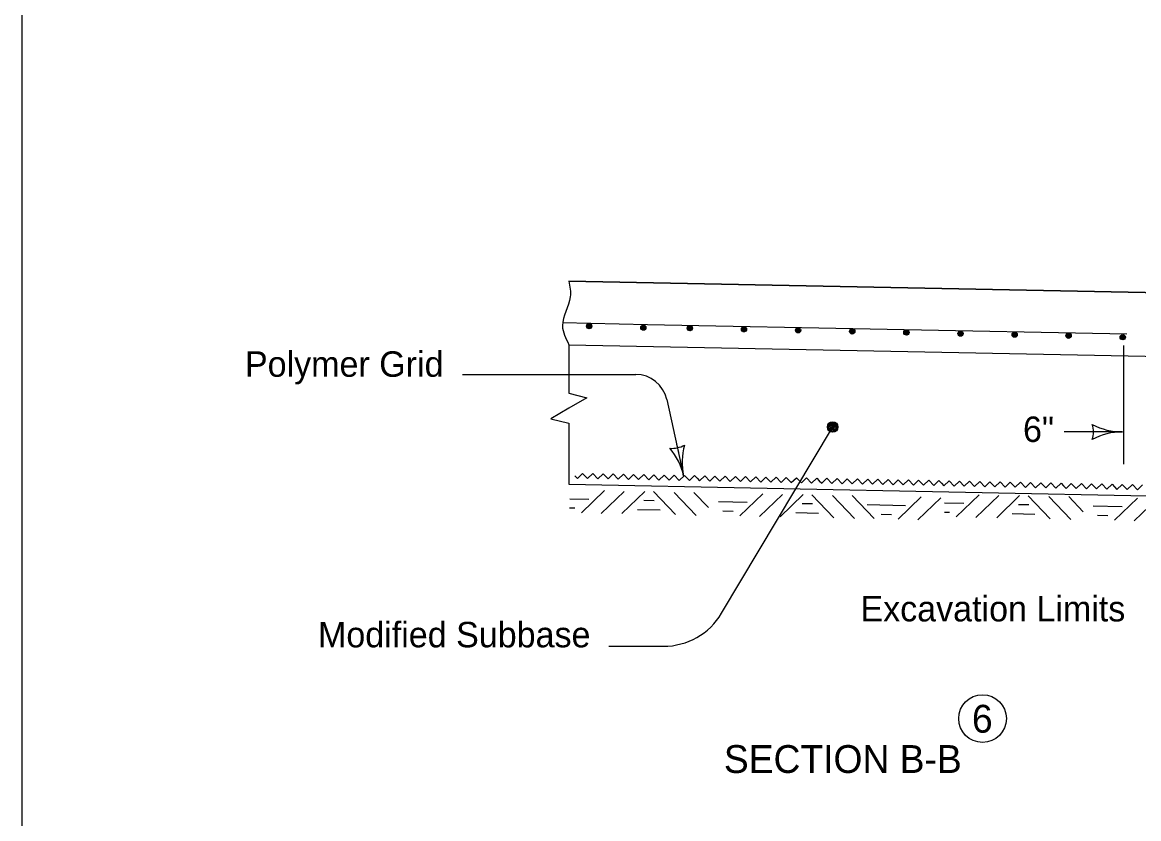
# Model space of a CAD drawing. Extents: x -2134934 to -2124557, y -2139046 to -2134021.
# Drawn here: x -2127734 to -2127033, y -2138041 to -2137540 of the extents above; entities that cross this region are included whole.
import ezdxf

# ---------------------------------------------------------------- set-up
doc = ezdxf.new("R2010")
doc.units = 0
for name, color, linetype in [('BridgeSuperStructureExisting', 7, 'Continuous'), ('dsnAlignmentStation', 7, 'Continuous'), ('dsnStdLabel', 7, 'Continuous')]:
    doc.layers.add(name, color=color, linetype=linetype)

msp = doc.modelspace()

# ---------------------------------------------------------------- linework, layer by layer
at = {"layer": 'BridgeSuperStructureExisting'}
for p, q in [((-2127017.9, -2137710.47), (-2127390.83, -2137702.98)), ((-2127390.83, -2137702.98), (-2127017.9, -2137710.47)), ((-2127341.36, -2137730.42), (-2127394.8, -2137729.34)), ((-2127040, -2137736.46), (-2127341.36, -2137730.42)), ((-2127390.83, -2137742.99), (-2127017.9, -2137750.47)), ((-2127390.83, -2137742.99), (-2127017.9, -2137750.47)), ((-2127390.83, -2137743.25), (-2127390.83, -2137773.51)), ((-2127041.9, -2137818.01), (-2127041.9, -2137743.54)), ((-2127457.64, -2137761.72), (-2127348.85, -2137761.72)), ((-2127390.83, -2137773.51), (-2127379.49, -2137776.34)), ((-2127379.49, -2137776.34), (-2127390.83, -2137782.96)), ((-2127329.32, -2137777.41), (-2127318.71, -2137825.54)), ((-2127390.83, -2137782.96), (-2127402.18, -2137789.58)), ((-2127402.18, -2137789.58), (-2127390.83, -2137792.41)), ((-2127390.83, -2137792.41), (-2127390.83, -2137830.73)), ((-2127294.85, -2137911.86), (-2127225.04, -2137795.08)), ((-2127042.89, -2137797.83), (-2127079.43, -2137797.83)), ((-2127323.1, -2137805.62), (-2127321.97, -2137810.73)), ((-2127390.83, -2137830.73), (-2126921.91, -2137840.14)), ((-2127368.56, -2137834.75), (-2127382.98, -2137848.6)), ((-2127356.12, -2137835.22), (-2127370.54, -2137849.08)), ((-2127343.11, -2137835.26), (-2127357.53, -2137849.11)), ((-2127337.7, -2137835.36), (-2127323.84, -2137849.79)), ((-2127324.69, -2137835.85), (-2127310.84, -2137850.27)), ((-2127312.24, -2137835.88), (-2127303.14, -2137845.35)), ((-2127269.03, -2137836.74), (-2127283.45, -2137850.6)), ((-2127256.58, -2137837.22), (-2127271.01, -2137851.07)), ((-2127243.57, -2137837.25), (-2127258, -2137851.11)), ((-2127238.16, -2137837.36), (-2127224.31, -2137851.79)), ((-2127225.16, -2137837.85), (-2127211.31, -2137852.27)), ((-2127212.71, -2137837.87), (-2127198.85, -2137852.3)), ((-2127132.96, -2137837.38), (-2127147.38, -2137851.24)), ((-2127120.51, -2137837.86), (-2127134.94, -2137851.71)), ((-2127107.5, -2137837.89), (-2127121.93, -2137851.75)), ((-2127102.09, -2137838), (-2127088.24, -2137852.42)), ((-2127169.49, -2137838.74), (-2127183.92, -2137852.6)), ((-2127157.05, -2137839.22), (-2127171.47, -2137853.07)), ((-2127089.09, -2137838.49), (-2127075.24, -2137852.91)), ((-2127076.64, -2137838.51), (-2127067.54, -2137847.99)), ((-2127033.43, -2137839.38), (-2127047.85, -2137853.24)), ((-2127020.98, -2137839.86), (-2127035.41, -2137853.71)), ((-2127365.65, -2137932.57), (-2127331.37, -2137932.57))]:
    msp.add_line(p, q, dxfattribs=at)
for points in [[(-2127379.58, -2137731.47), (-2127379.33, -2137730.91), (-2127379.06, -2137730.05), (-2127378.18, -2137729.88), (-2127377.41, -2137730), (-2127376.69, -2137730.55), (-2127376.76, -2137731.38), (-2127376.89, -2137732.25), (-2127377.58, -2137732.67), (-2127378.31, -2137732.75), (-2127379.27, -2137732.23), (-2127379.35, -2137731.6), (-2127379.13, -2137730.72), (-2127378.57, -2137730.01), (-2127377.75, -2137730.04), (-2127377.08, -2137730.59), (-2127377.01, -2137731.37), (-2127377.18, -2137732.24), (-2127377.67, -2137732.38), (-2127378.26, -2137732.55), (-2127378.98, -2137732.14), (-2127378.96, -2137731.51), (-2127378.84, -2137730.79), (-2127378.44, -2137730.26), (-2127377.71, -2137730.52), (-2127377.29, -2137731.07), (-2127377.27, -2137731.8), (-2127377.66, -2137731.99), (-2127378.1, -2137732.22), (-2127378.68, -2137731.86), (-2127378.81, -2137731.32), (-2127378.55, -2137730.84), (-2127378.01, -2137730.81), (-2127377.63, -2137731.06), (-2127377.5, -2137731.55), (-2127377.7, -2137731.79), (-2127378, -2137731.93), (-2127378.43, -2137731.67), (-2127378.51, -2137731.33), (-2127378.31, -2137730.99), (-2127378.02, -2137731.05), (-2127377.83, -2137731.3), (-2127377.84, -2137731.64), (-2127378.09, -2137731.63), (-2127378.22, -2137731.34)], [(-2127345.55, -2137732.4), (-2127345.3, -2137731.84), (-2127345.03, -2137730.97), (-2127344.15, -2137730.81), (-2127343.37, -2137730.93), (-2127342.66, -2137731.48), (-2127342.73, -2137732.31), (-2127342.86, -2137733.18), (-2127343.55, -2137733.6), (-2127344.28, -2137733.68), (-2127345.24, -2137733.16), (-2127345.32, -2137732.53), (-2127345.1, -2137731.65), (-2127344.54, -2137730.94), (-2127343.72, -2137730.96), (-2127343.05, -2137731.52), (-2127342.98, -2137732.3), (-2127343.15, -2137733.17), (-2127343.64, -2137733.3), (-2127344.23, -2137733.48), (-2127344.94, -2137733.07), (-2127344.92, -2137732.44), (-2127344.81, -2137731.71), (-2127344.4, -2137731.19), (-2127343.68, -2137731.45), (-2127343.26, -2137732), (-2127343.23, -2137732.73), (-2127343.62, -2137732.91), (-2127344.07, -2137733.14), (-2127344.64, -2137732.79), (-2127344.77, -2137732.25), (-2127344.52, -2137731.77), (-2127343.98, -2137731.73), (-2127343.6, -2137731.99), (-2127343.46, -2137732.48), (-2127343.67, -2137732.72), (-2127343.97, -2137732.85), (-2127344.39, -2137732.6), (-2127344.48, -2137732.26), (-2127344.28, -2137731.92), (-2127343.99, -2137731.98), (-2127343.8, -2137732.23), (-2127343.81, -2137732.57), (-2127344.05, -2137732.56), (-2127344.19, -2137732.26)], [(-2127313.29, -2137732.73), (-2127313.54, -2137732.17), (-2127313.81, -2137731.31), (-2127314.69, -2137731.13), (-2127315.46, -2137731.25), (-2127316.18, -2137731.81), (-2127316.11, -2137732.63), (-2127315.99, -2137733.51), (-2127315.29, -2137733.93), (-2127314.56, -2137734), (-2127313.6, -2137733.49), (-2127313.52, -2137732.85), (-2127313.74, -2137731.98), (-2127314.3, -2137731.27), (-2127315.12, -2137731.29), (-2127315.79, -2137731.85), (-2127315.86, -2137732.63), (-2127315.7, -2137733.5), (-2127315.2, -2137733.63), (-2127314.61, -2137733.81), (-2127313.9, -2137733.4), (-2127313.91, -2137732.77), (-2127314.03, -2137732.04), (-2127314.44, -2137731.51), (-2127315.16, -2137731.78), (-2127315.58, -2137732.33), (-2127315.6, -2137733.06), (-2127315.21, -2137733.24), (-2127314.77, -2137733.47), (-2127314.19, -2137733.12), (-2127314.07, -2137732.58), (-2127314.32, -2137732.1), (-2127314.86, -2137732.07), (-2127315.24, -2137732.32), (-2127315.37, -2137732.81), (-2127315.17, -2137733.05), (-2127314.87, -2137733.19), (-2127314.44, -2137732.93), (-2127314.36, -2137732.58), (-2127314.56, -2137732.25), (-2127314.85, -2137732.31), (-2127315.04, -2137732.56), (-2127315.03, -2137732.9), (-2127314.78, -2137732.89), (-2127314.65, -2137732.59)], [(-2127279.26, -2137733.41), (-2127279.51, -2137732.86), (-2127279.78, -2137731.98), (-2127280.66, -2137731.82), (-2127281.43, -2137731.94), (-2127282.15, -2137732.49), (-2127282.07, -2137733.32), (-2127281.95, -2137734.19), (-2127281.26, -2137734.61), (-2127280.53, -2137734.69), (-2127279.57, -2137734.17), (-2127279.49, -2137733.54), (-2127279.71, -2137732.66), (-2127280.27, -2137731.95), (-2127281.09, -2137731.98), (-2127281.76, -2137732.53), (-2127281.83, -2137733.31), (-2127281.66, -2137734.18), (-2127281.17, -2137734.32), (-2127280.58, -2137734.49), (-2127279.86, -2137734.08), (-2127279.89, -2137733.45), (-2127280, -2137732.72), (-2127280.4, -2137732.2), (-2127281.12, -2137732.46), (-2127281.55, -2137733.01), (-2127281.58, -2137733.74), (-2127281.18, -2137733.93), (-2127280.74, -2137734.16), (-2127280.16, -2137733.8), (-2127280.03, -2137733.26), (-2127280.29, -2137732.78), (-2127280.83, -2137732.75), (-2127281.21, -2137733), (-2127281.34, -2137733.49), (-2127281.14, -2137733.73), (-2127280.84, -2137733.87), (-2127280.41, -2137733.61), (-2127280.32, -2137733.27), (-2127280.53, -2137732.93), (-2127280.82, -2137732.99), (-2127281.01, -2137733.24), (-2127281, -2137733.58), (-2127280.75, -2137733.57), (-2127280.62, -2137733.28)], [(-2127245.23, -2137734.1), (-2127245.48, -2137733.54), (-2127245.75, -2137732.67), (-2127246.63, -2137732.5), (-2127247.4, -2137732.62), (-2127248.12, -2137733.18), (-2127248.04, -2137734), (-2127247.92, -2137734.88), (-2127247.23, -2137735.29), (-2127246.5, -2137735.37), (-2127245.54, -2137734.85), (-2127245.46, -2137734.22), (-2127245.68, -2137733.35), (-2127246.23, -2137732.63), (-2127247.06, -2137732.66), (-2127247.73, -2137733.22), (-2127247.8, -2137733.99), (-2127247.63, -2137734.87), (-2127247.14, -2137735), (-2127246.55, -2137735.17), (-2127245.83, -2137734.76), (-2127245.85, -2137734.14), (-2127245.97, -2137733.4), (-2127246.37, -2137732.88), (-2127247.09, -2137733.15), (-2127247.52, -2137733.7), (-2127247.54, -2137734.43), (-2127247.15, -2137734.61), (-2127246.7, -2137734.84), (-2127246.13, -2137734.48), (-2127246, -2137733.94), (-2127246.26, -2137733.46), (-2127246.79, -2137733.43), (-2127247.17, -2137733.68), (-2127247.31, -2137734.17), (-2127247.11, -2137734.41), (-2127246.81, -2137734.55), (-2127246.38, -2137734.29), (-2127246.29, -2137733.95), (-2127246.5, -2137733.62), (-2127246.79, -2137733.67), (-2127246.97, -2137733.92), (-2127246.96, -2137734.26), (-2127246.72, -2137734.26), (-2127246.58, -2137733.96)], [(-2127211.19, -2137734.78), (-2127211.45, -2137734.22), (-2127211.71, -2137733.35), (-2127212.59, -2137733.18), (-2127213.37, -2137733.31), (-2127214.08, -2137733.86), (-2127214.01, -2137734.69), (-2127213.89, -2137735.56), (-2127213.19, -2137735.97), (-2127212.46, -2137736.05), (-2127211.51, -2137735.54), (-2127211.42, -2137734.91), (-2127211.64, -2137734.03), (-2127212.2, -2137733.32), (-2127213.03, -2137733.34), (-2127213.69, -2137733.9), (-2127213.77, -2137734.68), (-2127213.6, -2137735.55), (-2127213.1, -2137735.68), (-2127212.51, -2137735.86), (-2127211.8, -2137735.45), (-2127211.82, -2137734.82), (-2127211.93, -2137734.09), (-2127212.34, -2137733.57), (-2127213.06, -2137733.83), (-2127213.49, -2137734.38), (-2127213.51, -2137735.11), (-2127213.12, -2137735.29), (-2127212.67, -2137735.53), (-2127212.1, -2137735.17), (-2127211.97, -2137734.63), (-2127212.22, -2137734.15), (-2127212.76, -2137734.11), (-2127213.14, -2137734.37), (-2127213.28, -2137734.86), (-2127213.07, -2137735.1), (-2127212.78, -2137735.23), (-2127212.35, -2137734.98), (-2127212.26, -2137734.64), (-2127212.46, -2137734.3), (-2127212.75, -2137734.36), (-2127212.94, -2137734.61), (-2127212.93, -2137734.95), (-2127212.69, -2137734.94), (-2127212.55, -2137734.64)], [(-2127177.16, -2137735.47), (-2127177.41, -2137734.91), (-2127177.68, -2137734.04), (-2127178.56, -2137733.87), (-2127179.33, -2137733.99), (-2127180.05, -2137734.54), (-2127179.98, -2137735.37), (-2127179.85, -2137736.24), (-2127179.16, -2137736.66), (-2127178.43, -2137736.74), (-2127177.47, -2137736.22), (-2127177.39, -2137735.59), (-2127177.61, -2137734.72), (-2127178.17, -2137734), (-2127178.99, -2137734.02), (-2127179.66, -2137734.58), (-2127179.73, -2137735.36), (-2127179.56, -2137736.24), (-2127179.07, -2137736.37), (-2127178.48, -2137736.54), (-2127177.76, -2137736.13), (-2127177.78, -2137735.5), (-2127177.9, -2137734.77), (-2127178.31, -2137734.25), (-2127179.03, -2137734.52), (-2127179.45, -2137735.06), (-2127179.48, -2137735.79), (-2127179.08, -2137735.97), (-2127178.64, -2137736.21), (-2127178.06, -2137735.85), (-2127177.94, -2137735.31), (-2127178.19, -2137734.83), (-2127178.73, -2137734.8), (-2127179.11, -2137735.05), (-2127179.24, -2137735.54), (-2127179.04, -2137735.78), (-2127178.74, -2137735.92), (-2127178.31, -2137735.66), (-2127178.23, -2137735.32), (-2127178.43, -2137734.98), (-2127178.72, -2137735.04), (-2127178.91, -2137735.29), (-2127178.9, -2137735.63), (-2127178.65, -2137735.62), (-2127178.52, -2137735.32)], [(-2127143.13, -2137736.15), (-2127143.38, -2137735.59), (-2127143.65, -2137734.72), (-2127144.53, -2137734.55), (-2127145.3, -2137734.67), (-2127146.02, -2137735.23), (-2127145.94, -2137736.05), (-2127145.82, -2137736.92), (-2127145.13, -2137737.34), (-2127144.4, -2137737.42), (-2127143.44, -2137736.9), (-2127143.36, -2137736.27), (-2127143.58, -2137735.4), (-2127144.14, -2137734.69), (-2127144.96, -2137734.71), (-2127145.63, -2137735.26), (-2127145.7, -2137736.04), (-2127145.53, -2137736.91), (-2127145.04, -2137737.05), (-2127144.45, -2137737.23), (-2127143.73, -2137736.82), (-2127143.75, -2137736.18), (-2127143.87, -2137735.46), (-2127144.27, -2137734.93), (-2127144.99, -2137735.2), (-2127145.42, -2137735.74), (-2127145.44, -2137736.47), (-2127145.05, -2137736.66), (-2127144.61, -2137736.89), (-2127144.03, -2137736.53), (-2127143.9, -2137735.99), (-2127144.16, -2137735.51), (-2127144.7, -2137735.48), (-2127145.08, -2137735.74), (-2127145.21, -2137736.23), (-2127145.01, -2137736.46), (-2127144.71, -2137736.6), (-2127144.28, -2137736.35), (-2127144.2, -2137736), (-2127144.4, -2137735.67), (-2127144.69, -2137735.72), (-2127144.87, -2137735.97), (-2127144.87, -2137736.31), (-2127144.62, -2137736.31), (-2127144.49, -2137736.01)], [(-2127109.09, -2137736.83), (-2127109.35, -2137736.27), (-2127109.61, -2137735.4), (-2127110.49, -2137735.23), (-2127111.27, -2137735.35), (-2127111.99, -2137735.91), (-2127111.91, -2137736.74), (-2127111.79, -2137737.61), (-2127111.1, -2137738.03), (-2127110.36, -2137738.1), (-2127109.4, -2137737.59), (-2127109.33, -2137736.95), (-2127109.55, -2137736.08), (-2127110.1, -2137735.37), (-2127110.93, -2137735.39), (-2127111.59, -2137735.95), (-2127111.67, -2137736.73), (-2127111.5, -2137737.6), (-2127111.01, -2137737.73), (-2127110.42, -2137737.91), (-2127109.7, -2137737.5), (-2127109.72, -2137736.87), (-2127109.83, -2137736.14), (-2127110.24, -2137735.62), (-2127110.96, -2137735.88), (-2127111.38, -2137736.43), (-2127111.41, -2137737.16), (-2127111.02, -2137737.34), (-2127110.57, -2137737.57), (-2127110, -2137737.21), (-2127109.87, -2137736.68), (-2127110.12, -2137736.2), (-2127110.66, -2137736.16), (-2127111.04, -2137736.42), (-2127111.18, -2137736.91), (-2127110.98, -2137737.15), (-2127110.68, -2137737.28), (-2127110.25, -2137737.03), (-2127110.16, -2137736.68), (-2127110.36, -2137736.35), (-2127110.66, -2137736.41), (-2127110.84, -2137736.65), (-2127110.84, -2137737), (-2127110.59, -2137736.99), (-2127110.45, -2137736.69)], [(-2127078.22, -2137737.52), (-2127077.97, -2137736.96), (-2127077.7, -2137736.09), (-2127076.82, -2137735.92), (-2127076.05, -2137736.04), (-2127075.33, -2137736.6), (-2127075.41, -2137737.43), (-2127075.53, -2137738.3), (-2127076.22, -2137738.71), (-2127076.95, -2137738.79), (-2127077.91, -2137738.28), (-2127077.99, -2137737.64), (-2127077.77, -2137736.77), (-2127077.21, -2137736.06), (-2127076.39, -2137736.09), (-2127075.72, -2137736.64), (-2127075.65, -2137737.42), (-2127075.82, -2137738.29), (-2127076.31, -2137738.42), (-2127076.9, -2137738.6), (-2127077.62, -2137738.19), (-2127077.6, -2137737.56), (-2127077.48, -2137736.83), (-2127077.08, -2137736.31), (-2127076.35, -2137736.57), (-2127075.93, -2137737.12), (-2127075.91, -2137737.85), (-2127076.3, -2137738.04), (-2127076.74, -2137738.26), (-2127077.32, -2137737.91), (-2127077.45, -2137737.37), (-2127077.19, -2137736.89), (-2127076.65, -2137736.86), (-2127076.27, -2137737.11), (-2127076.14, -2137737.6), (-2127076.34, -2137737.84), (-2127076.64, -2137737.98), (-2127077.07, -2137737.72), (-2127077.15, -2137737.37), (-2127076.95, -2137737.04), (-2127076.66, -2137737.09), (-2127076.47, -2137737.35), (-2127076.48, -2137737.68), (-2127076.73, -2137737.68), (-2127076.86, -2137737.39)], [(-2127044.19, -2137738.45), (-2127043.94, -2137737.89), (-2127043.67, -2137737.02), (-2127042.79, -2137736.86), (-2127042.02, -2137736.97), (-2127041.3, -2137737.53), (-2127041.37, -2137738.36), (-2127041.5, -2137739.23), (-2127042.19, -2137739.65), (-2127042.92, -2137739.72), (-2127043.88, -2137739.21), (-2127043.96, -2137738.57), (-2127043.74, -2137737.7), (-2127043.18, -2137736.99), (-2127042.36, -2137737.01), (-2127041.69, -2137737.56), (-2127041.62, -2137738.35), (-2127041.79, -2137739.22), (-2127042.28, -2137739.35), (-2127042.87, -2137739.53), (-2127043.59, -2137739.12), (-2127043.57, -2137738.48), (-2127043.45, -2137737.76), (-2127043.04, -2137737.24), (-2127042.32, -2137737.5), (-2127041.9, -2137738.05), (-2127041.87, -2137738.78), (-2127042.27, -2137738.96), (-2127042.71, -2137739.19), (-2127043.29, -2137738.83), (-2127043.41, -2137738.3), (-2127043.16, -2137737.81), (-2127042.62, -2137737.78), (-2127042.24, -2137738.04), (-2127042.11, -2137738.53), (-2127042.31, -2137738.77), (-2127042.61, -2137738.9), (-2127043.04, -2137738.65), (-2127043.12, -2137738.3), (-2127042.92, -2137737.97), (-2127042.63, -2137738.03), (-2127042.44, -2137738.27), (-2127042.45, -2137738.61), (-2127042.7, -2137738.61), (-2127042.83, -2137738.31)], [(-2127225.32, -2137797.8), (-2127224.2, -2137797.3), (-2127222.46, -2137796.76), (-2127222.13, -2137795), (-2127222.37, -2137793.45), (-2127223.48, -2137792.02), (-2127225.13, -2137792.16), (-2127226.87, -2137792.41), (-2127227.71, -2137793.8), (-2127227.86, -2137795.26), (-2127226.83, -2137797.18), (-2127225.56, -2137797.33), (-2127223.82, -2137796.89), (-2127222.4, -2137795.78), (-2127222.44, -2137794.13), (-2127223.56, -2137792.8), (-2127225.12, -2137792.65), (-2127226.86, -2137792.99), (-2127227.12, -2137793.97), (-2127227.47, -2137795.15), (-2127226.66, -2137796.59), (-2127225.39, -2137796.55), (-2127223.94, -2137796.32), (-2127222.89, -2137795.5), (-2127223.42, -2137794.06), (-2127224.52, -2137793.22), (-2127225.98, -2137793.17), (-2127226.34, -2137793.95), (-2127226.81, -2137794.84), (-2127226.09, -2137795.99), (-2127225.01, -2137796.25), (-2127224.05, -2137795.74), (-2127223.98, -2137794.66), (-2127224.49, -2137793.9), (-2127225.47, -2137793.64), (-2127225.95, -2137794.04), (-2127226.23, -2137794.63), (-2127225.71, -2137795.49), (-2127225.03, -2137795.66), (-2127224.36, -2137795.26), (-2127224.47, -2137794.67), (-2127224.97, -2137794.3), (-2127225.65, -2137794.32), (-2127225.64, -2137794.81), (-2127225.04, -2137795.08)], [(-2127387.02, -2137825.4), (-2127385.45, -2137827.03), (-2127382.19, -2137823.9), (-2127379.05, -2137827.16), (-2127375.79, -2137824.02), (-2127372.65, -2137827.29), (-2127369.39, -2137824.15), (-2127366.25, -2137827.42), (-2127362.99, -2137824.28), (-2127359.86, -2137827.55), (-2127356.59, -2137824.41), (-2127353.46, -2137827.67), (-2127350.19, -2137824.54), (-2127347.06, -2137827.8), (-2127343.8, -2137824.67), (-2127340.66, -2137827.93), (-2127337.4, -2137824.8), (-2127334.26, -2137828.06), (-2127331, -2137824.92), (-2127327.86, -2137828.19), (-2127324.6, -2137825.05), (-2127321.46, -2137828.32), (-2127318.2, -2137825.18), (-2127315.07, -2137828.44), (-2127311.8, -2137825.31), (-2127310.23, -2137826.94)], [(-2127310.23, -2137826.94), (-2127308.67, -2137828.57), (-2127305.4, -2137825.44), (-2127302.27, -2137828.7), (-2127299, -2137825.57), (-2127295.87, -2137828.83), (-2127292.61, -2137825.69), (-2127289.47, -2137828.96), (-2127286.21, -2137825.82), (-2127283.07, -2137829.09), (-2127279.81, -2137825.95), (-2127276.67, -2137829.21), (-2127273.41, -2137826.08), (-2127270.27, -2137829.34), (-2127267.01, -2137826.21), (-2127263.88, -2137829.47), (-2127260.61, -2137826.34), (-2127257.48, -2137829.6), (-2127254.21, -2137826.47), (-2127251.08, -2137829.73), (-2127247.81, -2137826.59), (-2127244.68, -2137829.86), (-2127241.42, -2137826.72), (-2127238.28, -2137829.99), (-2127235.02, -2137826.85), (-2127233.45, -2137828.48)], [(-2127233.45, -2137828.48), (-2127231.88, -2137830.11), (-2127228.62, -2137826.98), (-2127225.48, -2137830.24), (-2127222.22, -2137827.11), (-2127219.08, -2137830.37), (-2127215.82, -2137827.24), (-2127212.69, -2137830.5), (-2127209.42, -2137827.36), (-2127206.29, -2137830.63), (-2127203.02, -2137827.49), (-2127199.89, -2137830.76), (-2127196.62, -2137827.62), (-2127193.49, -2137830.88), (-2127190.23, -2137827.75), (-2127187.09, -2137831.01), (-2127183.83, -2137827.88), (-2127180.69, -2137831.14), (-2127177.43, -2137828.01), (-2127174.29, -2137831.27), (-2127171.03, -2137828.13), (-2127167.89, -2137831.4), (-2127164.63, -2137828.26), (-2127161.5, -2137831.53), (-2127158.23, -2137828.39), (-2127156.66, -2137830.02)], [(-2127156.63, -2137830.12), (-2127155.06, -2137831.76), (-2127151.8, -2137828.62), (-2127148.66, -2137831.88), (-2127145.4, -2137828.75), (-2127142.27, -2137832.01), (-2127139, -2137828.88), (-2127135.87, -2137832.14), (-2127132.6, -2137829.01), (-2127129.47, -2137832.27), (-2127126.2, -2137829.13), (-2127123.07, -2137832.4), (-2127119.81, -2137829.26), (-2127116.67, -2137832.53), (-2127113.41, -2137829.39), (-2127110.27, -2137832.66), (-2127107.01, -2137829.52), (-2127103.87, -2137832.78), (-2127100.61, -2137829.65), (-2127097.47, -2137832.91), (-2127094.21, -2137829.78), (-2127091.08, -2137833.04), (-2127087.81, -2137829.91), (-2127084.68, -2137833.17), (-2127081.41, -2137830.03), (-2127079.85, -2137831.67)], [(-2127079.85, -2137831.67), (-2127078.28, -2137833.3), (-2127075.01, -2137830.16), (-2127071.88, -2137833.43), (-2127068.62, -2137830.29), (-2127065.48, -2137833.55), (-2127062.22, -2137830.42), (-2127059.08, -2137833.68), (-2127055.82, -2137830.55), (-2127052.68, -2137833.81), (-2127049.42, -2137830.68), (-2127046.29, -2137833.94), (-2127043.02, -2137830.8), (-2127039.89, -2137834.07), (-2127036.62, -2137830.93), (-2127033.49, -2137834.2), (-2127030.22, -2137831.06)], [(-2127390.28, -2137839.79), (-2127378.25, -2137840.03)], [(-2127343.78, -2137840.74), (-2127337.24, -2137840.87)], [(-2127296.78, -2137841.66), (-2127278.72, -2137842.02)], [(-2127244.24, -2137842.74), (-2127237.71, -2137842.87)], [(-2127203.24, -2137843.54), (-2127179.18, -2137844.02)], [(-2127154.68, -2137842.42), (-2127142.65, -2137842.66)], [(-2127108.17, -2137843.38), (-2127101.64, -2137843.51)], [(-2127061.18, -2137844.3), (-2127043.12, -2137844.66)], [(-2127390.39, -2137845.58), (-2127387.13, -2137845.65)], [(-2127347.72, -2137846.52), (-2127333.53, -2137846.8)], [(-2127294.13, -2137847.52), (-2127287.6, -2137847.65)], [(-2127248.19, -2137848.52), (-2127234, -2137848.8)], [(-2127194.59, -2137849.51), (-2127188.06, -2137849.64)], [(-2127154.79, -2137848.22), (-2127151.53, -2137848.29)], [(-2127112.12, -2137849.16), (-2127097.93, -2137849.44)], [(-2127058.53, -2137850.15), (-2127052, -2137850.28)]]:
    msp.add_lwpolyline(points, dxfattribs=at)
for centre, radius in [((-2127378.06, -2137731.35), 1.65), ((-2127344.03, -2137732.28), 1.65), ((-2127314.81, -2137732.61), 1.65), ((-2127280.78, -2137733.29), 1.65), ((-2127246.74, -2137733.97), 1.65), ((-2127212.71, -2137734.66), 1.65), ((-2127178.68, -2137735.34), 1.65), ((-2127144.65, -2137736.02), 1.65), ((-2127110.61, -2137736.71), 1.65), ((-2127076.71, -2137737.4), 1.65), ((-2127042.67, -2137738.32), 1.65), ((-2127225.06, -2137794.76), 3.31), ((-2127130.82, -2137978.01), 15)]:
    msp.add_circle(centre, radius, dxfattribs=at)
for centre, radius, start, end in [((-2127348.85, -2137781.72), 20, 12.43134, 90), ((-2127076.58, -2137797.83), 15.52, 342.26665, 17.73335), ((-2127042.89, -2137757.66), 40.18, 241.92751, 270), ((-2127076.58, -2137797.83), 15.52, 342.26665, 17.73335), ((-2127042.89, -2137757.66), 40.18, 241.92751, 270), ((-2127042.89, -2137838.01), 40.18, 90, 118.07249), ((-2127042.89, -2137838.01), 40.18, 90, 118.07249), ((-2127325.95, -2137792.64), 15.52, 264.68499, 300.15169), ((-2127357.94, -2137834.18), 40.18, 12.41834, 40.49083), ((-2127279.47, -2137816.9), 40.18, 164.34585, 192.41834), ((-2127331.37, -2137890.03), 42.54, 270, 329.12488)]:
    msp.add_arc(centre, radius, start, end, dxfattribs=at)
msp.add_spline([(-2127390.83, -2137702.98), (-2127390.01, -2137713), (-2127394.89, -2137731.04), (-2127390.83, -2137742.99)], degree=3, dxfattribs=at)
msp.add_spline([(-2127390.83, -2137702.98), (-2127390.01, -2137713), (-2127394.89, -2137731.04), (-2127390.83, -2137742.99)], degree=3, dxfattribs=at)
at = {"layer": 'dsnAlignmentStation'}
msp.add_lwpolyline([(-2127734.44, -2137035.95), (-2124599.45, -2137035.95), (-2124599.45, -2139045.94), (-2127734.44, -2139045.94)], close=True, dxfattribs=at)

# ---------------------------------------------------------------- texts
at = {"layer": 'dsnStdLabel'}
for s, height, p in [('Polymer Grid', 16, (-2127594.49, -2137763.17)), ('6"', 16, (-2127105.37, -2137804.15)), ('Excavation Limits', 16, (-2127207.54, -2137916.95)), ('Modified Subbase', 16, (-2127548.57, -2137933.24)), ('6', 17.5, (-2127137.48, -2137986.88)), ('SECTION B-B', 17.5, (-2127293.42, -2138012.21))]:
    msp.add_text(s, height=height, dxfattribs=at).set_placement(p)

doc.saveas('drawing.dxf')
